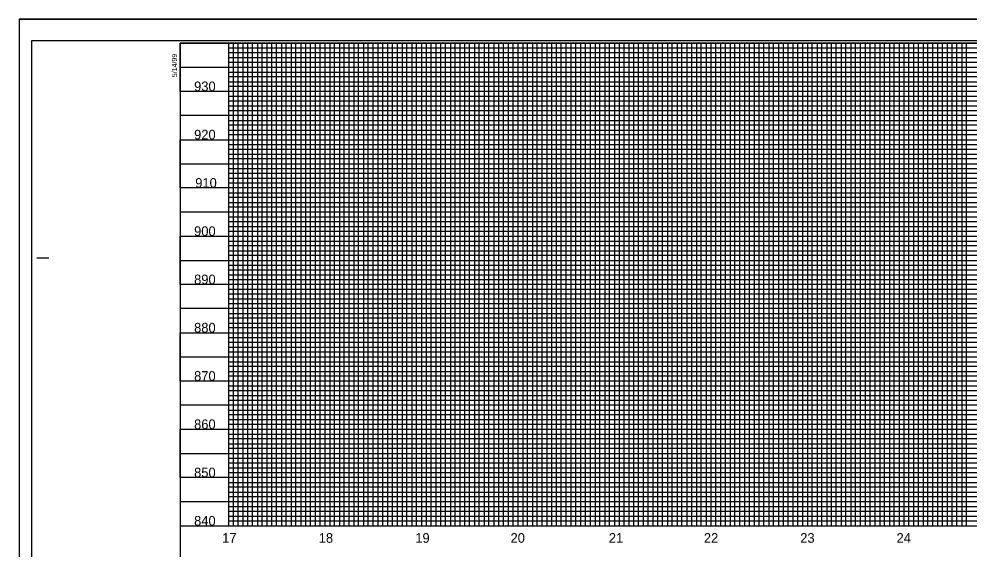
# Model space of a CAD drawing. Extents: x 1967929 to 1975641, y 546296 to 568534.
# Drawn here: x 1969864 to 1970849, y 567984 to 568534 of the extents above; entities that cross this region are included whole.
import ezdxf

# ---------------------------------------------------------------- set-up
doc = ezdxf.new("R2010")
doc.units = 0
for name, color, linetype in [('Exist Vertical Profile Horizontal Axis Label Major', 7, 'Continuous'), ('Exist Vertical Profile Vertical Axis Label', 7, 'Continuous'), ('Old_Level_41', 7, 'Continuous'), ('Old_Level_43', 7, 'Continuous'), ('Old_Level_46', 7, 'Continuous'), ('Scratch_Level_3', 7, 'Continuous'), ('Sheet Cutting Line CELL', 7, 'Continuous'), ('Sheet Plot Border Inside CELL', 7, 'Continuous'), ('Sheet Plot Border Outside CELL', 7, 'Continuous'), ('Sheet Profile CELL', 7, 'Continuous'), ('Sheet Profile Grid Major CELL', 7, 'Continuous'), ('Sheet Profile Grid Middle CELL', 7, 'Continuous'), ('Sheet Profile Grid Minor CELL', 7, 'Continuous')]:
    doc.layers.add(name, color=color, linetype=linetype)

msp = doc.modelspace()

# ---------------------------------------------------------------- linework, layer by layer
at = {"layer": 'Old_Level_41'}
msp.add_line((1969882.95, 568286.36), (1969895.45, 568286.36), dxfattribs=at)
at = {"layer": 'Old_Level_43'}
msp.add_line((1970081.45, 568498.86), (1970081.45, 568498.86), dxfattribs=at)
at = {"layer": 'Old_Level_46'}
for p, q in [((1970031.45, 568508.86), (1970031.45, 568508.86)), ((1970031.45, 567983.86), (1970031.45, 567983.86))]:
    msp.add_line(p, q, dxfattribs=at)
at = {"layer": 'Scratch_Level_3'}
for points in [[(1970081.45, 568508.86), (1970081.45, 568008.86), (1971481.45, 568008.86), (1971481.5, 568312.51), (1971331.45, 568312.51), (1971331.4, 568508.86)], [(1970081.45, 568508.86), (1970081.45, 568008.86), (1971331.45, 568008.86), (1971331.45, 568277.21), (1971331.45, 568277.21), (1971331.45, 568508.86)], [(1970081.45, 568508.86), (1970081.45, 568008.86), (1971481.45, 568008.86), (1971481.5, 568312.53), (1971331.45, 568312.51), (1971331.4, 568508.86)]]:
    msp.add_lwpolyline(points, close=True, dxfattribs=at)
at = {"layer": 'Sheet Cutting Line CELL'}
for q in [(1971548.45, 568533.86), (1969864.45, 567433.86)]:
    msp.add_line((1969864.45, 568533.86), q, dxfattribs=at)
at = {"layer": 'Sheet Plot Border Inside CELL'}
msp.add_lwpolyline([(1969877.45, 567456.31), (1971543.95, 567456.31), (1971543.95, 568511.41), (1969877.45, 568511.41)], close=True, dxfattribs=at)
at = {"layer": 'Sheet Plot Border Outside CELL'}
msp.add_lwpolyline([(1969864.45, 567433.86), (1971548.45, 567433.86), (1971548.45, 568533.86), (1969864.45, 568533.86)], close=True, dxfattribs=at)
at = {"layer": 'Sheet Profile CELL'}
msp.add_line((1970031.45, 568008.86), (1971531.45, 568008.86), dxfattribs=at)
msp.add_lwpolyline([(1971531.45, 568508.86), (1970031.45, 568508.86), (1970031.45, 567458.86), (1971531.45, 567458.86)], close=True, dxfattribs=at)
at = {"layer": 'Sheet Profile Grid Major CELL'}
for points in [[(1971331.45, 568458.86), (1970031.45, 568458.86), (1970031.45, 568508.86), (1971331.45, 568508.86)], [(1970081.45, 568508.86), (1970081.45, 568008.86), (1970131.45, 568008.86), (1970131.45, 568508.86)], [(1970181.45, 568508.86), (1970181.45, 568008.86), (1970231.45, 568008.86), (1970231.45, 568508.86)], [(1970281.45, 568508.86), (1970281.45, 568008.86), (1970331.45, 568008.86), (1970331.45, 568508.86)], [(1970381.45, 568508.86), (1970381.45, 568008.86), (1970431.45, 568008.86), (1970431.45, 568508.86)], [(1970481.45, 568508.86), (1970481.45, 568008.86), (1970531.45, 568008.86), (1970531.45, 568508.86)], [(1970581.45, 568508.86), (1970581.45, 568008.86), (1970631.45, 568008.86), (1970631.45, 568508.86)], [(1970681.45, 568508.86), (1970681.45, 568008.86), (1970731.45, 568008.86), (1970731.45, 568508.86)], [(1970781.45, 568508.86), (1970781.45, 568008.86), (1970831.45, 568008.86), (1970831.45, 568508.86)], [(1971331.45, 568358.86), (1970031.45, 568358.86), (1970031.45, 568408.86), (1971331.45, 568408.86)], [(1971531.45, 568258.86), (1970031.45, 568258.86), (1970031.45, 568308.86), (1971331.4, 568308.86)], [(1971531.45, 568258.86), (1970031.45, 568258.86), (1970031.45, 568308.86), (1971531.45, 568308.86)], [(1971531.45, 568158.86), (1970031.45, 568158.86), (1970031.45, 568208.86), (1971531.45, 568208.86)], [(1971531.45, 568058.86), (1970031.45, 568058.86), (1970031.45, 568108.86), (1971531.45, 568108.86)]]:
    msp.add_lwpolyline(points, dxfattribs=at)
at = {"layer": 'Sheet Profile Grid Middle CELL'}
for points in [[(1970031.45, 568508.86), (1970031.45, 568483.86), (1971331.45, 568483.86)], [(1970106.45, 568008.86), (1970106.45, 568508.86)], [(1970156.45, 568508.86), (1970156.45, 568008.86), (1970206.45, 568008.86), (1970206.45, 568508.86)], [(1970256.45, 568508.86), (1970256.45, 568008.86), (1970306.45, 568008.86), (1970306.45, 568508.86)], [(1970356.45, 568508.86), (1970356.45, 568008.86), (1970406.45, 568008.86), (1970406.45, 568508.86)], [(1970456.45, 568508.86), (1970456.45, 568008.86), (1970506.45, 568008.86), (1970506.45, 568508.86)], [(1970556.45, 568508.86), (1970556.45, 568008.86), (1970606.45, 568008.86), (1970606.45, 568508.86)], [(1970656.45, 568508.86), (1970656.45, 568008.86), (1970706.45, 568008.86), (1970706.45, 568508.86)], [(1970756.45, 568508.86), (1970756.45, 568008.86), (1970806.45, 568008.86), (1970806.45, 568508.86)], [(1971331.45, 568433.86), (1970031.45, 568433.86), (1970031.45, 568383.86), (1971331.45, 568383.86)], [(1971331.45, 568333.86), (1970031.45, 568333.86), (1970031.45, 568283.86), (1971331.4, 568283.86)], [(1971331.45, 568333.86), (1970031.45, 568333.86), (1970031.45, 568283.86), (1971531.45, 568283.86)], [(1971531.45, 568233.86), (1970031.45, 568233.86), (1970031.45, 568183.86), (1971531.45, 568183.86)], [(1971531.45, 568133.86), (1970031.45, 568133.86), (1970031.45, 568083.86), (1971531.45, 568083.86)], [(1971531.45, 568033.86), (1970031.45, 568033.86)]]:
    msp.add_lwpolyline(points, dxfattribs=at)
at = {"layer": 'Sheet Profile Grid Minor CELL'}
for points in [[(1970081.45, 568503.86), (1971331.45, 568503.86)], [(1970086.45, 568508.86), (1970086.45, 568008.86), (1970091.45, 568008.86), (1970091.45, 568508.86)], [(1970096.45, 568508.86), (1970096.45, 568008.86), (1970101.45, 568008.86), (1970101.45, 568508.86)], [(1970111.45, 568508.86), (1970111.45, 568008.86), (1970116.45, 568008.86), (1970116.45, 568508.86)], [(1970121.45, 568508.86), (1970121.45, 568008.86), (1970126.45, 568008.86), (1970126.45, 568508.86)], [(1970136.45, 568508.86), (1970136.45, 568008.86), (1970141.45, 568008.86), (1970141.45, 568508.86)], [(1970146.45, 568508.86), (1970146.45, 568008.86), (1970151.45, 568008.86), (1970151.45, 568508.86)], [(1970161.45, 568508.86), (1970161.45, 568008.86), (1970166.45, 568008.86), (1970166.45, 568508.86)], [(1970171.45, 568508.86), (1970171.45, 568008.86), (1970176.45, 568008.86), (1970176.45, 568508.86)], [(1970186.45, 568508.86), (1970186.45, 568008.86), (1970191.45, 568008.86), (1970191.45, 568508.86)], [(1970196.45, 568508.86), (1970196.45, 568008.86), (1970201.45, 568008.86), (1970201.45, 568508.86)], [(1970211.45, 568508.86), (1970211.45, 568008.86), (1970216.45, 568008.86), (1970216.45, 568508.86)], [(1970221.45, 568508.86), (1970221.45, 568008.86), (1970226.45, 568008.86), (1970226.45, 568508.86)], [(1970236.45, 568508.86), (1970236.45, 568008.86), (1970241.45, 568008.86), (1970241.45, 568508.86)], [(1970246.45, 568008.86), (1970251.45, 568008.86), (1970251.45, 568508.86)], [(1970246.45, 568508.86), (1970246.45, 568008.86)], [(1970261.45, 568508.86), (1970261.45, 568008.86), (1970266.45, 568008.86), (1970266.45, 568508.86)], [(1970271.45, 568508.86), (1970271.45, 568008.86), (1970276.45, 568008.86), (1970276.45, 568508.86)], [(1970286.45, 568508.86), (1970286.45, 568008.86), (1970291.45, 568008.86), (1970291.45, 568508.86)], [(1970296.45, 568508.86), (1970296.45, 568008.86), (1970301.45, 568008.86), (1970301.45, 568508.86)], [(1970311.45, 568508.86), (1970311.45, 568008.86), (1970316.45, 568008.86), (1970316.45, 568508.86)], [(1970321.45, 568508.86), (1970321.45, 568008.86), (1970326.45, 568008.86), (1970326.45, 568508.86)], [(1970336.45, 568508.86), (1970336.45, 568008.86), (1970341.45, 568008.86), (1970341.45, 568508.86)], [(1970346.45, 568508.86), (1970346.45, 568008.86), (1970351.45, 568008.86), (1970351.45, 568508.86)], [(1970361.45, 568508.86), (1970361.45, 568008.86), (1970366.45, 568008.86), (1970366.45, 568508.86)], [(1970371.45, 568508.86), (1970371.45, 568008.86), (1970376.45, 568008.86), (1970376.45, 568508.86)], [(1970386.45, 568508.86), (1970386.45, 568008.86), (1970391.45, 568008.86), (1970391.45, 568508.86)], [(1970396.45, 568508.86), (1970396.45, 568008.86), (1970401.45, 568008.86), (1970401.45, 568508.86)], [(1970411.45, 568508.86), (1970411.45, 568008.86), (1970426.45, 568008.86), (1970426.45, 568508.86)], [(1970416.45, 568508.86), (1970416.45, 568008.86), (1970421.45, 568008.86), (1970421.45, 568508.86)], [(1970436.45, 568508.86), (1970436.45, 568008.86), (1970441.45, 568008.86), (1970441.45, 568508.86)], [(1970446.45, 568508.86), (1970446.45, 568008.86), (1970451.45, 568008.86), (1970451.45, 568508.86)], [(1970461.45, 568508.86), (1970461.45, 568008.86), (1970466.45, 568008.86), (1970466.45, 568508.86)], [(1970471.45, 568508.86), (1970471.45, 568008.86), (1970476.45, 568008.86), (1970476.45, 568508.86)], [(1970486.45, 568508.86), (1970486.45, 568008.86), (1970491.45, 568008.86), (1970491.45, 568508.86)], [(1970496.45, 568508.86), (1970496.45, 568008.86), (1970501.45, 568008.86), (1970501.45, 568508.86)], [(1970511.45, 568508.86), (1970511.45, 568008.86), (1970516.45, 568008.86), (1970516.45, 568508.86)], [(1970521.45, 568508.86), (1970521.45, 568008.86), (1970526.45, 568008.86), (1970526.45, 568508.86)], [(1970536.45, 568508.86), (1970536.45, 568008.86), (1970541.45, 568008.86), (1970541.45, 568508.86)], [(1970546.45, 568508.86), (1970546.45, 568008.86), (1970551.45, 568008.86), (1970551.45, 568508.86)], [(1970561.45, 568508.86), (1970561.45, 568008.86)], [(1970566.45, 568508.86), (1970566.45, 568008.86), (1970571.45, 568008.86), (1970571.45, 568508.86)], [(1970576.45, 568508.86), (1970576.45, 568008.86), (1970586.45, 568008.86), (1970586.45, 568508.86)], [(1970591.45, 568508.86), (1970591.45, 568008.86), (1970596.45, 568008.86), (1970596.45, 568508.86)], [(1970601.45, 568508.86), (1970601.45, 568008.86)], [(1970611.45, 568008.86), (1970611.45, 568508.86)], [(1970616.45, 568508.86), (1970616.45, 568008.86), (1970621.45, 568008.86), (1970621.45, 568508.86)], [(1970626.45, 568508.86), (1970626.45, 568008.86), (1970636.45, 568008.86), (1970636.45, 568508.86)], [(1970641.45, 568508.86), (1970641.45, 568008.86), (1970641.45, 568008.86), (1970646.45, 568008.86), (1970646.45, 568508.86)], [(1970651.45, 568508.86), (1970651.45, 568008.86), (1970661.45, 568008.86), (1970661.45, 568508.86)], [(1970666.45, 568508.86), (1970666.45, 568008.86), (1970671.45, 568008.86), (1970671.45, 568508.86)], [(1970676.45, 568508.86), (1970676.45, 568008.86), (1970686.45, 568008.86), (1970686.45, 568508.86)], [(1970691.45, 568508.86), (1970691.45, 568008.86), (1970696.45, 568008.86), (1970696.45, 568508.86)], [(1970701.45, 568508.86), (1970701.45, 568008.86), (1970711.45, 568008.86), (1970711.45, 568508.86)], [(1970716.45, 568508.86), (1970716.45, 568008.86), (1970721.45, 568008.86), (1970721.45, 568508.86)], [(1970726.45, 568508.86), (1970726.45, 568008.86), (1970736.45, 568008.86), (1970736.45, 568508.86)], [(1970741.45, 568508.86), (1970741.45, 568008.86), (1970746.45, 568008.86), (1970746.45, 568508.86)], [(1970751.45, 568508.86), (1970751.45, 568008.86), (1970761.45, 568008.86), (1970761.45, 568508.86)], [(1970766.45, 568508.86), (1970766.45, 568008.86), (1970771.45, 568008.86), (1970771.45, 568508.86)], [(1970776.45, 568508.86), (1970776.45, 568008.86), (1970786.45, 568008.86), (1970786.45, 568508.86)], [(1970791.45, 568508.86), (1970791.45, 568008.86)], [(1970791.45, 568008.86), (1970796.45, 568008.86), (1970796.45, 568508.86)], [(1970801.45, 568508.86), (1970801.45, 568008.86), (1970811.45, 568008.86), (1970811.45, 568508.86)], [(1970816.45, 568508.86), (1970816.45, 568008.86), (1970821.45, 568008.86), (1970821.45, 568508.86)], [(1970826.45, 568508.86), (1970826.45, 568008.86), (1970836.45, 568008.86), (1970836.45, 568508.86)], [(1970841.45, 568508.86), (1970841.45, 568008.86), (1970846.45, 568008.86), (1970846.45, 568508.86)], [(1971331.45, 568498.86), (1970081.45, 568498.86), (1970081.45, 568493.86), (1971331.45, 568493.86)], [(1971331.45, 568488.86), (1970081.45, 568488.86), (1970081.45, 568478.86), (1971331.45, 568478.86)], [(1971331.45, 568473.86), (1970081.45, 568473.86), (1970081.45, 568468.86), (1971331.45, 568468.86)], [(1971331.45, 568463.86), (1970081.45, 568463.86), (1970081.45, 568453.86), (1971331.45, 568453.86)], [(1971331.45, 568448.86), (1970081.45, 568448.86), (1970081.45, 568443.86), (1971331.45, 568443.86)], [(1971331.45, 568438.86), (1970081.45, 568438.86), (1970081.45, 568428.86), (1971331.45, 568428.86)], [(1971331.45, 568423.86), (1970081.45, 568423.86), (1970081.45, 568418.86), (1971331.45, 568418.86)], [(1971331.45, 568413.86), (1970081.45, 568413.86), (1970081.45, 568403.86), (1971331.45, 568403.86)], [(1971331.45, 568398.86), (1970081.45, 568398.86), (1970081.45, 568393.86), (1971331.45, 568393.86)], [(1971331.45, 568388.86), (1970081.45, 568388.86), (1970081.45, 568378.86), (1971331.45, 568378.86)], [(1971331.45, 568373.86), (1970081.45, 568373.86), (1970081.45, 568368.86), (1971331.45, 568368.86)], [(1971331.45, 568363.86), (1970081.45, 568363.86), (1970081.45, 568353.86), (1971331.45, 568353.86)], [(1971331.45, 568348.86), (1970081.45, 568348.86), (1970081.45, 568343.86), (1971331.45, 568343.86)], [(1971331.45, 568338.86), (1970081.45, 568338.86), (1970081.45, 568328.86), (1971331.45, 568328.86)], [(1971331.45, 568323.86), (1970081.45, 568323.86), (1970081.45, 568318.86), (1971331.45, 568318.86)], [(1971331.45, 568313.86), (1970081.45, 568313.86), (1970081.45, 568303.86), (1971331.4, 568303.86)], [(1971331.45, 568313.86), (1970081.45, 568313.86), (1970081.45, 568303.86), (1971481.45, 568303.86)], [(1971331.4, 568298.86), (1970081.45, 568298.86), (1970081.45, 568293.86), (1971331.4, 568293.86)], [(1971481.45, 568298.86), (1970081.45, 568298.86), (1970081.45, 568293.86), (1971481.45, 568293.86)], [(1971331.4, 568288.86), (1970081.45, 568288.86), (1970081.45, 568278.86), (1971331.4, 568278.86)], [(1971481.45, 568288.86), (1970081.45, 568288.86), (1970081.45, 568278.86), (1971481.45, 568278.86)], [(1971481.45, 568273.86), (1970081.45, 568273.86), (1970081.45, 568268.86), (1971481.45, 568268.86)], [(1971481.45, 568263.86), (1970081.45, 568263.86), (1970081.45, 568253.86), (1971481.45, 568253.86)], [(1971481.45, 568248.86), (1970081.45, 568248.86), (1970081.45, 568243.86), (1971481.45, 568243.86)], [(1971481.45, 568238.86), (1970081.45, 568238.86), (1970081.45, 568228.86), (1971481.45, 568228.86)], [(1971481.45, 568223.86), (1970081.45, 568223.86), (1970081.45, 568218.86), (1971481.45, 568218.86)], [(1971481.45, 568213.86), (1970081.45, 568213.86)], [(1970081.45, 568203.86), (1971481.45, 568203.86)], [(1971481.45, 568198.86), (1970081.45, 568198.86), (1970081.45, 568193.86), (1971481.45, 568193.86)], [(1971481.45, 568188.86), (1970081.45, 568188.86)], [(1970081.45, 568178.86), (1971481.45, 568178.86)], [(1971481.45, 568173.86), (1970081.45, 568173.86), (1970081.45, 568168.86), (1971481.45, 568168.86)], [(1971481.45, 568163.86), (1970081.45, 568163.86), (1970081.45, 568153.86), (1971481.45, 568153.86)], [(1971481.45, 568148.86), (1970081.45, 568148.86), (1970081.45, 568143.86), (1971481.45, 568143.86)], [(1971481.45, 568138.86), (1970081.45, 568138.86), (1970081.45, 568128.86), (1971481.45, 568128.86)], [(1971481.45, 568123.86), (1970081.45, 568123.86), (1970081.45, 568118.86), (1971481.45, 568118.86)], [(1971481.45, 568113.86), (1970081.45, 568113.86), (1970081.45, 568103.86), (1971481.45, 568103.86)], [(1971481.45, 568098.86), (1970081.45, 568098.86), (1970081.45, 568093.86), (1971481.45, 568093.86)], [(1971481.45, 568088.86), (1970081.45, 568088.86), (1970081.45, 568078.86), (1971481.45, 568078.86)], [(1971481.45, 568073.86), (1970081.45, 568073.86), (1970081.45, 568068.86), (1971481.45, 568068.86)], [(1971481.45, 568063.86), (1970081.45, 568063.86), (1970081.45, 568053.86), (1971481.45, 568053.86)], [(1971481.45, 568048.86), (1970081.45, 568048.86), (1970081.45, 568043.86), (1971481.45, 568043.86)], [(1971481.45, 568038.86), (1970081.45, 568038.86), (1970081.45, 568028.86), (1971481.45, 568028.86)], [(1971481.45, 568023.86), (1970081.45, 568023.86), (1970081.45, 568018.86), (1971481.45, 568018.86)], [(1971481.45, 568013.86), (1970081.45, 568013.86), (1970081.45, 568008.86), (1971481.45, 568008.86)]]:
    msp.add_lwpolyline(points, dxfattribs=at)

# ---------------------------------------------------------------- texts
at = {"layer": 'Exist Vertical Profile Horizontal Axis Label Major'}
for s, p in [('17', (1970074.99, 567991.36)), ('18', (1970175.11, 567991.36)), ('19', (1970275.16, 567991.36)), ('20', (1970373.84, 567991.36)), ('21', (1970475.68, 567991.36)), ('22', (1970574.22, 567991.36)), ('23', (1970674.06, 567991.36)), ('24', (1970773.9, 567991.36))]:
    msp.add_text(s, height=10, dxfattribs=at).set_placement(p)
at = {"layer": 'Exist Vertical Profile Vertical Axis Label'}
for s, p in [('930', (1970045.92, 568459.11)), ('920', (1970045.92, 568409.11)), ('910', (1970047.11, 568359.11)), ('900', (1970045.92, 568309.11)), ('890', (1970045.92, 568259.11)), ('880', (1970045.92, 568209.11)), ('870', (1970045.92, 568159.11)), ('860', (1970045.92, 568109.11)), ('850', (1970045.92, 568059.11)), ('840', (1970045.92, 568009.11))]:
    msp.add_text(s, height=10, dxfattribs=at).set_placement(p)
at = {"layer": 'Sheet Profile CELL'}
msp.add_text('5/14/99', height=5.25, rotation=90, dxfattribs=at).set_placement((1970028.2, 568473.66))

doc.saveas('drawing.dxf')
